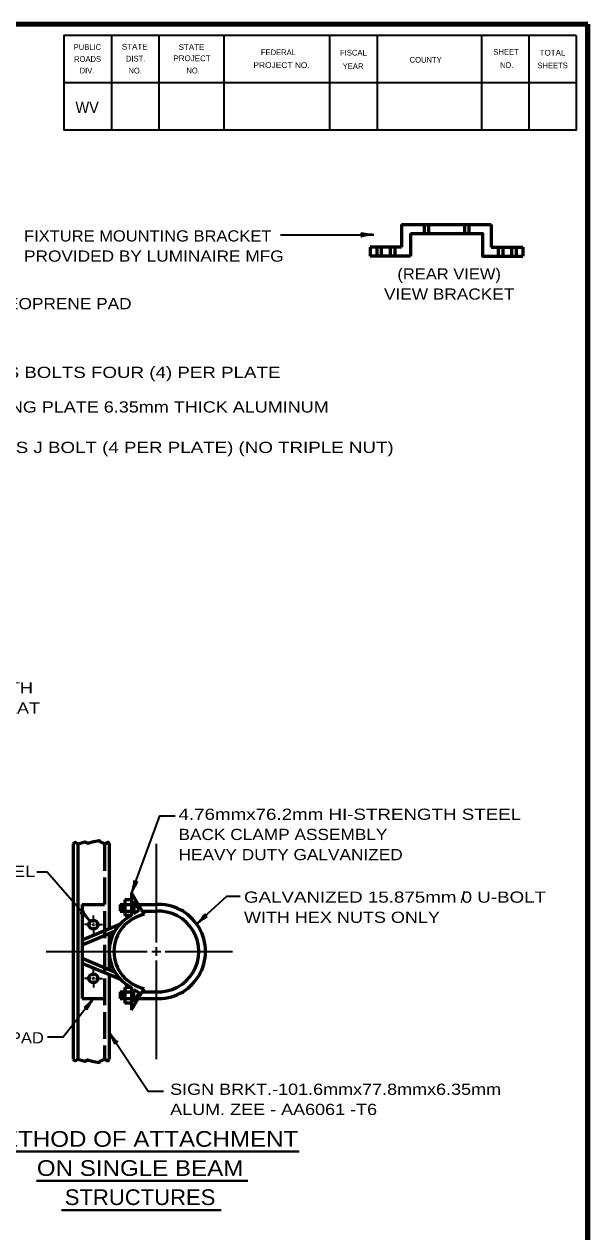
# Model space of a CAD drawing. Extents: x -94 to 762, y -50 to 494.
# Drawn here: x 604.6 to 755.4, y 164.1 to 487.4 of the extents above; entities that cross this region are included whole.
import ezdxf
from ezdxf.enums import TextEntityAlignment as Align

# ---------------------------------------------------------------- set-up
doc = ezdxf.new("R2010")
doc.units = 0
doc.header["$LTSCALE"] = 1.2
doc.linetypes.add('LONG_DASHED', pattern=[7.5, 6, -1.5])
doc.layers.add('1', color=7, linetype='Continuous', lineweight=53)
doc.layers.add('61', color=7, linetype='Continuous', lineweight=35)

msp = doc.modelspace()

# ---------------------------------------------------------------- linework, layer by layer
at = {"layer": '1', "lineweight": 158}
msp.add_line((755.402, -38.728), (755.402, 487.372), dxfattribs=at)
at = {"layer": '1', "lineweight": 13}
msp.add_line((755.402, -38.728), (755.402, 487.372), dxfattribs=at)
at = {"layer": '1'}
for p, q in [((705.574, 433.702), (729.574, 433.702)), ((705.574, 433.702), (705.574, 427.702)), ((711.574, 433.702), (711.574, 431.302)), ((712.774, 433.702), (712.774, 431.302)), ((722.374, 433.702), (722.374, 431.302)), ((723.574, 433.702), (723.574, 431.302)), ((729.574, 433.702), (729.574, 427.702)), ((707.974, 431.302), (707.974, 425.302)), ((705.574, 427.702), (697.174, 427.702)), ((697.174, 427.702), (697.174, 425.302)), ((698.938, 427.702), (698.938, 425.302)), ((700.138, 427.702), (700.138, 425.302)), ((702.538, 427.702), (702.538, 425.302)), ((703.738, 427.702), (703.738, 425.302)), ((729.574, 427.702), (737.974, 427.702)), ((731.41, 427.702), (731.41, 425.302)), ((732.61, 427.702), (732.61, 425.302)), ((735.01, 427.702), (735.01, 425.302)), ((736.21, 427.702), (736.21, 425.302)), ((737.974, 427.702), (737.974, 425.302)), ((707.974, 425.302), (697.174, 425.302)), ((617.694, 267.951), (617.694, 210.351)), ((618.894, 267.951), (618.894, 210.351)), ((627.294, 267.951), (627.294, 245.251)), ((631.494, 252.948), (631.494, 248.751)), ((633.294, 252.948), (631.494, 252.948)), ((633.294, 254.751), (633.294, 248.751)), ((633.294, 254.751), (636.719, 249.043)), ((633.894, 252.585), (633.894, 249.351)), ((633.894, 252.585), (635.321, 250.207)), ((620.094, 251.751), (626.094, 251.751)), ((630.294, 251.748), (633.294, 251.748)), ((630.294, 251.748), (630.294, 249.951)), ((630.294, 249.951), (633.294, 249.951)), ((630.894, 251.448), (630.894, 250.251)), ((633.894, 249.351), (635.321, 250.207)), ((635.096, 251.748), (639.785, 251.748)), ((636.174, 249.951), (639.894, 249.951)), ((620.094, 242.251), (630.181, 246.454)), ((633.294, 248.751), (631.494, 248.751)), ((620.094, 240.951), (628.768, 244.565)), ((627.294, 243.951), (627.294, 234.351)), ((620.094, 237.351), (628.768, 233.737)), ((620.094, 236.051), (630.181, 231.848)), ((627.294, 233.051), (627.294, 210.351)), ((631.494, 229.551), (631.494, 225.354)), ((633.294, 229.551), (631.494, 229.551)), ((633.294, 229.551), (633.294, 223.551)), ((620.094, 226.551), (626.094, 226.551)), ((630.294, 228.351), (633.294, 228.351)), ((630.294, 228.351), (630.294, 226.554)), ((630.294, 226.554), (633.294, 226.554)), ((630.894, 228.051), (630.894, 226.854)), ((633.294, 223.551), (636.719, 229.259)), ((633.894, 228.951), (635.321, 228.095)), ((633.894, 225.717), (633.894, 228.951)), ((633.894, 225.717), (635.321, 228.095)), ((635.096, 226.554), (639.785, 226.554)), ((636.174, 228.351), (639.894, 228.351)), ((633.294, 225.354), (631.494, 225.354))]:
    msp.add_line(p, q, dxfattribs=at)
at = {"layer": '1', "lineweight": 35}
for p, q in [((673.125, 431.013), (698.134, 431.013)), ((639.894, 267.951), (639.894, 241.551)), ((622.494, 246.351), (620.694, 246.351)), ((622.794, 246.351), (623.394, 246.351)), ((623.094, 246.951), (623.094, 248.751)), ((623.094, 246.651), (623.094, 246.051)), ((623.094, 245.751), (623.094, 243.951)), ((623.694, 246.351), (625.494, 246.351)), ((639.894, 240.351), (639.894, 237.951)), ((610.494, 239.151), (627.294, 239.151)), ((627.594, 239.151), (637.494, 239.151)), ((638.694, 239.151), (641.094, 239.151)), ((639.894, 236.751), (639.894, 210.351)), ((642.294, 239.151), (660.294, 239.151)), ((623.094, 232.551), (623.094, 234.351)), ((622.494, 231.951), (620.694, 231.951)), ((622.794, 231.951), (623.394, 231.951)), ((623.094, 232.251), (623.094, 231.651)), ((623.094, 231.351), (623.094, 229.551)), ((623.694, 231.951), (625.494, 231.951))]:
    msp.add_line(p, q, dxfattribs=at)
at = {"layer": '1', "linetype": 'LONG_DASHED'}
msp.add_line((626.094, 267.951), (626.094, 210.351), dxfattribs=at)
at = {"layer": '1', "lineweight": 40}
for p, q in [((593.16, 185.581), (678.142, 185.581)), ((607.874, 177.744), (664.438, 177.744)), ((614.563, 169.907), (657.292, 169.907))]:
    msp.add_line(p, q, dxfattribs=at)
at = {"layer": '1', "lineweight": 158}
msp.add_lwpolyline([(755.402, 487.372), (-36.298, 487.272), (-36.198, -38.728)], dxfattribs=at)
at = {"layer": '1'}
for points in [[(707.974, 431.302), (727.174, 431.302), (727.174, 425.302), (737.974, 425.302)], [(617.694, 267.951), (618.25, 268.411), (618.894, 267.951), (620.758, 268.495), (621.594, 268.16), (622.764, 268.495), (624.604, 268.829), (624.771, 268.578), (626.094, 267.951), (627.028, 268.411), (627.294, 267.951)], [(620.094, 251.751), (620.094, 239.151), (620.094, 226.551)], [(617.694, 210.351), (618.25, 209.891), (618.894, 210.351), (620.758, 209.807), (621.594, 210.142), (622.764, 209.807), (624.604, 209.473), (624.771, 209.724), (626.094, 210.351), (627.028, 209.891), (627.294, 210.351)]]:
    msp.add_lwpolyline(points, dxfattribs=at)
at = {"layer": '1', "lineweight": 35}
for points in [[(633.294, 254.751), (640.884, 275.474), (644.984, 275.474)], [(622.245, 247.2), (610.689, 260.372), (607.962, 260.372)], [(650.719, 246.519), (658.781, 253.971), (662.381, 253.971)], [(623.094, 226.551), (614.989, 216.265), (610.789, 216.265)], [(627.294, 217.504), (637.785, 201.763), (641.884, 201.763)]]:
    msp.add_lwpolyline(points, dxfattribs=at)
at = {"layer": '1'}
for centre in [(623.094, 246.351), (623.094, 231.951)]:
    msp.add_circle(centre, 1.2, dxfattribs=at)
for centre, radius, start, end in [((638.652, 239.151), 10.079, 101.05672, 258.94328), ((640.476, 239.151), 12.618, 266.52859, 93.47141), ((640.476, 239.151), 10.818, 266.52859, 93.47141), ((637.974, 239.151), 10.68, 115.98923, 244.01077)]:
    msp.add_arc(centre, radius, start, end, dxfattribs=at)
at = {"layer": '1', "lineweight": 40}
for centre, major_axis, ratio, start_param, end_param in [((696.825, 430.681), (2.143, 0.187), 0.122415, 0.8963533, 3.1415927), ((696.79, 431.267), (2.108, -0.211), 0.07063, 3.1407148, 5.41811), ((633.433, 256.095), (-0.561, -2.077), 0.122415, 0.8963533, 3.1415927), ((633.433, 256.095), (-0.561, -2.077), 0.122415, 0.8963533, 3.1415927), ((633.995, 255.926), (0.923, 1.907), 0.07063, 6.2823074, 8.5597026), ((633.995, 255.926), (0.923, 1.907), 0.07063, 6.2823074, 8.5597026), ((621.133, 247.965), (1.554, -1.487), 0.122415, 0.8963533, 3.1415927), ((621.133, 247.965), (1.554, -1.487), 0.122415, 0.8963533, 3.1415927), ((621.55, 248.378), (-1.232, 1.723), 0.07063, 6.2823074, 8.5597026), ((621.55, 248.378), (-1.232, 1.723), 0.07063, 6.2823074, 8.5597026), ((651.456, 247.651), (-1.446, -1.592), 0.122415, 0.8963533, 3.1415927), ((651.456, 247.651), (-1.446, -1.592), 0.122415, 0.8963533, 3.1415927), ((651.879, 247.245), (-1.691, -1.276), 0.07063, 3.1407148, 5.41811), ((651.879, 247.245), (-1.691, -1.276), 0.07063, 3.1407148, 5.41811), ((622.062, 225.652), (1.47, 1.525), 0.07063, 3.1407148, 5.41811), ((622.544, 225.317), (1.179, 1.799), 0.122415, 0.8963533, 3.1415927), ((627.828, 216.244), (0.994, -1.871), 0.07063, 6.2823074, 8.5597026), ((627.828, 216.244), (0.994, -1.871), 0.07063, 6.2823074, 8.5597026), ((628.296, 216.598), (-1.344, 1.679), 0.122415, 0.8963533, 3.1415927), ((628.296, 216.598), (-1.344, 1.679), 0.122415, 0.8963533, 3.1415927)]:
    msp.add_ellipse(centre, major_axis=major_axis, ratio=ratio, start_param=start_param, end_param=end_param, dxfattribs=at)
at = {"layer": '61'}
for p, q in [((627.902, 484.372), (627.902, 458.972)), ((640.602, 484.372), (640.602, 458.972)), ((658.002, 484.372), (658.002, 458.972)), ((686.302, 484.372), (686.302, 458.972)), ((699.002, 484.372), (699.002, 458.972)), ((726.902, 484.372), (726.902, 458.972)), ((739.602, 484.372), (739.602, 458.972)), ((752.302, 471.672), (615.202, 471.672))]:
    msp.add_line(p, q, dxfattribs=at)
for points in [[(752.302, 484.372), (615.202, 484.372), (615.202, 458.972)], [(752.302, 484.372), (752.302, 458.972), (615.202, 458.972)]]:
    msp.add_lwpolyline(points, dxfattribs=at)

# ---------------------------------------------------------------- texts
at = {"layer": '1'}
for s, height, width, p in [('WV', 3.048, 0.95, (618.302, 463.572)), ('FIXTURE MOUNTING BRACKET', 3, 1.1, (604.531, 429.192)), ('PROVIDED BY LUMINAIRE MFG', 3, 1.15, (604.531, 423.792)), ('RUBBER OR NEOPRENE PAD', 3, 1.15, (567.941, 411.062)), ('7.94mm STAINLESS BOLTS FOUR (4) PER PLATE', 3, 1.25, (556.113, 392.671)), ('FIXTURE MOUNTING PLATE 6.35mm THICK ALUMINUM', 3, 1.2, (559.808, 383.416)), ('6.35mm STAINLESS J BOLT (4 PER PLATE) (NO TRIPLE NUT)', 3, 1.25, (558.545, 372.587)), ('GALV. U-BOLT & NUTS WITH', 3, 1.2, (541.122, 308.22)), ('STAINLESS STEEL AND FLAT', 3, 1.2, (541.122, 302.82)), ('4.76mmx76.2mm HI-STRENGTH STEEL', 3, 1.25, (645.873, 274.389)), ('BACK CLAMP ASSEMBLY', 3, 1.15, (645.873, 268.989)), ('HEAVY DUTY GALVANIZED', 3, 1.15, (645.873, 263.589)), ('15.88mm 0 STN. STEEL', 3, 1.25, (552.399, 259.082)), ('GALVANIZED 15.875mm 0 U-BOLT', 3, 1.25, (663.385, 252.211)), ('WITH HEX NUTS ONLY', 3, 1.2, (663.385, 246.811)), ('FABREEKA PAD', 3, 1.1, (575.986, 214.551)), ('SIGN BRKT.-101.6mmx77.8mmx6.35mm', 3, 1.2, (643.624, 200.783)), ('ALUM. ZEE - AA6061 -T6', 3, 1.2, (643.624, 195.383))]:
    msp.add_text(s, height=height, dxfattribs=dict(at, width=width)).set_placement(p)
for s, height, width, p in [('(REAR VIEW)', 3, 1.1, (718.295, 419.026)), ('VIEW BRACKET', 3, 1.15, (718.295, 413.626)), ('METHOD OF ATTACHMENT', 4.2, 1.15, (635.583, 186.885)), ('ON SINGLE BEAM', 4.2, 1.15, (635.583, 179.085)), ('STRUCTURES', 4.2, 1.05, (635.583, 171.285))]:
    msp.add_text(s, height=height, dxfattribs=dict(at, width=width)).set_placement(p, align=Align.CENTER)
msp.add_text('/', height=3, dxfattribs=at).set_placement((721.354, 252.198))
at = {"layer": '61'}
for s, height, rotation, p in [('PUBLIC', 1.525, 0.033, (617.802, 480.472)), ('ROADS', 1.525, 0.124, (617.902, 477.272)), ('DIST.', 1.525, 0.056, (631.802, 477.372)), ('FEDERAL', 1.523, 0.007, (667.902, 479.072)), ('FISCAL', 1.525, 359.942, (689.102, 478.972)), ('COUNTY', 1.523, 0.069, (707.702, 477.072)), ('SHEET', 1.525, 0.059, (730.102, 479.172)), ('DIV.', 1.525, 359.932, (619.402, 474.172)), ('YEAR', 1.523, 0.105, (689.802, 475.372)), ('SHEETS', 1.523, 359.959, (741.902, 475.572))]:
    msp.add_text(s, height=height, rotation=rotation, dxfattribs=at).set_placement(p)
for s, rotation, width, p in [('STATE', 0.059, 1.05, (630.702, 480.572)), ('STATE', 0.059, 1.05, (645.902, 480.472)), ('PROJECT', 359.908, 1.05, (644.502, 477.472)), ('TOTAL', 359.926, 1.05, (742.502, 478.972)), ('NO.', 359.852, 0.9, (632.502, 474.172)), ('NO.', 0.225, 0.9, (648.002, 474.172)), ('PROJECT NO.', 359.922, 1.1, (665.902, 475.672)), ('NO.', 359.852, 0.9, (731.902, 475.672))]:
    msp.add_text(s, height=1.525, rotation=rotation, dxfattribs=dict(at, width=width)).set_placement(p)

doc.saveas('drawing.dxf')
